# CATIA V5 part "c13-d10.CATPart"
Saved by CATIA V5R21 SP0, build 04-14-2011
Part number: Part1
Bounding box of the stored display mesh (mm): x -49.986 to 49.986, y -49.986 to 49.986, z 0 to 320
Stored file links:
  D:\CATIA V5R21 E-RESOURCES\CATIA-V5R21\catia-v5r21-Prts\c13_catia_v5r21_prt\c13_catia_v5r21_figr_13-37 & 38\c13-d10.CATPart
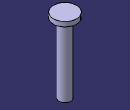
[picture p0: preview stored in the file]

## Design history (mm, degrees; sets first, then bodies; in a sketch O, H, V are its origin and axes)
Body1 (main body)
  Sketch1 on yz-plane, origin (0, 0, 0), H (0, 1, 0), V (0, 0, 1)
    axis line L1 (0, 0) -> (0, 409.3493)
    line L2 (0, 0) -> (25, 0)
    line L3 (25, 0) -> (25, 300)
    line L4 (25, 300) -> (50, 300)
    line L5 (50, 300) -> (50, 320)
    line L6 (50, 320) -> (0, 320)
    point P6 (0, 320)
    line L7 (0, 320) -> (0, 0)
    "Radius" L5 L1 = 50
    "Radius" L3 L1 = 25
    length L3 = 300
    length L5 = 20
    vertical: L1 V, L3 V, L5 V, L7 V
    horizontal: L2 H, L4 H, L6 H
    coincidence: P6 L1
  Shaft1: profile Sketch1, axis Sketch1.L1, angle 360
